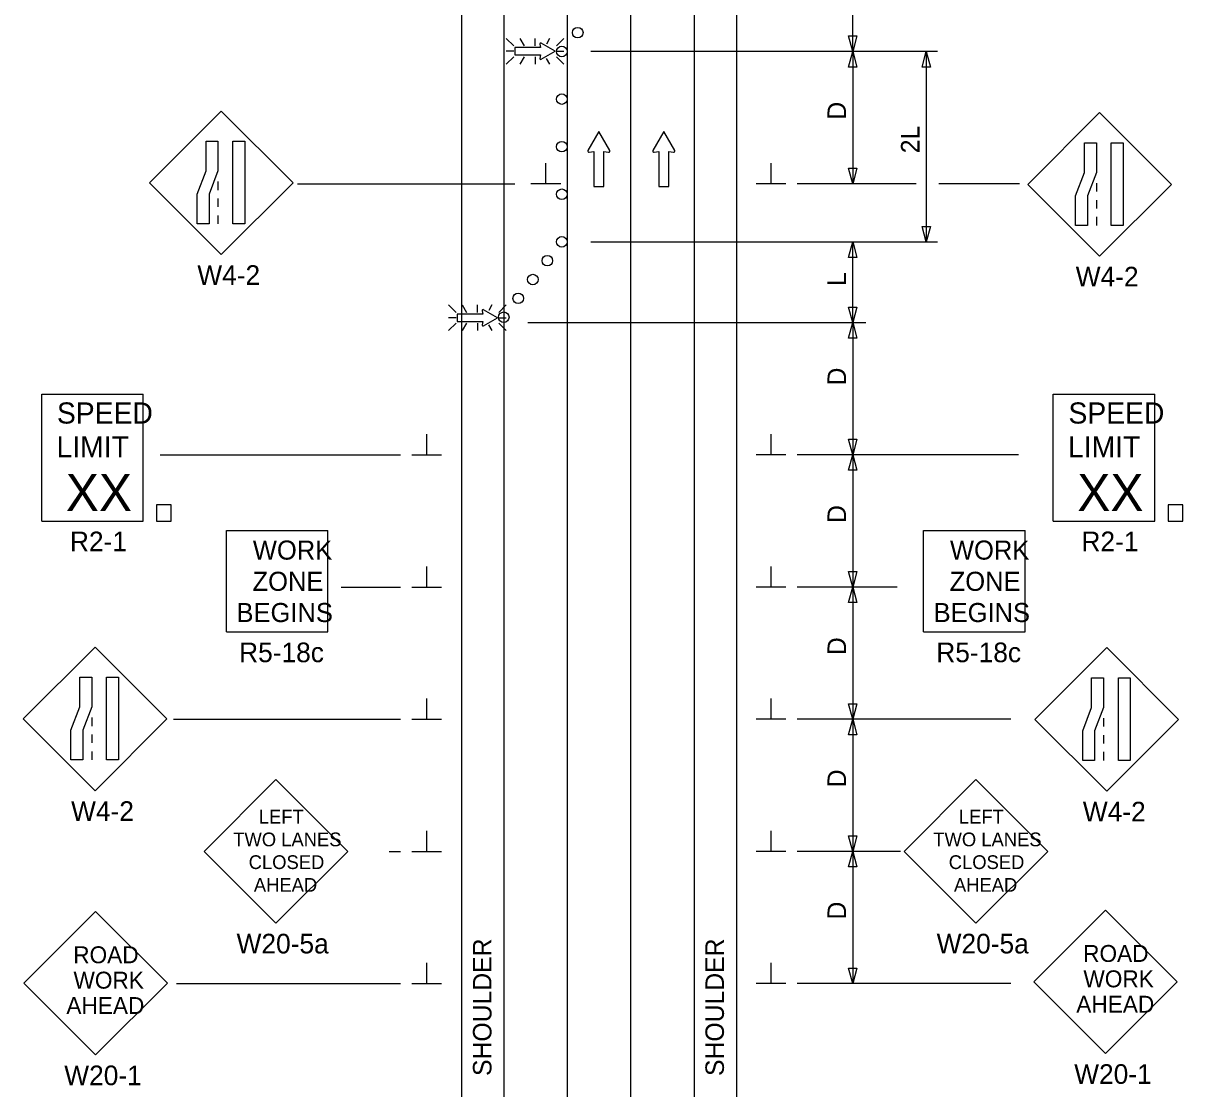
# Model space of a CAD drawing. Extents: x 16745 to 18475, y 7012 to 8195.
# Drawn here: x 16821.7 to 17260.2, y 7436.3 to 7839.4 of the extents above; entities that cross this region are included whole.
import ezdxf

# ---------------------------------------------------------------- set-up
doc = ezdxf.new("R2010")
doc.units = 0
for name, color, linetype in [('ALI_LEGAL_EX', 7, 'Continuous'), ('MT_SCRATCH_LEVEL_E', 7, 'Continuous'), ('PAVT_EDGE_EX', 7, 'Continuous'), ('TRAFFIC_SIGNS_PR', 7, 'Continuous'), ('TYPICAL_TEXT_DIMEN_PR', 7, 'Continuous')]:
    doc.layers.add(name, color=color, linetype=linetype)

msp = doc.modelspace()

# ---------------------------------------------------------------- linework, layer by layer
at = {"layer": 'ALI_LEGAL_EX'}
for p, q in [((17027.37, 8191.42), (17027.37, 7362.23)), ((17051.37, 8191.42), (17051.37, 7362.23)), ((17051.37, 8191.42), (17051.37, 7362.23))]:
    msp.add_line(p, q, dxfattribs=at)
for points in [[(17027.37, 7791.42), (17027.37, 7766.42)], [(17051.37, 7791.42), (17051.37, 7766.42)], [(17027.37, 7691.42), (17027.37, 7666.42)], [(17051.37, 7691.42), (17051.37, 7666.42)], [(17027.37, 7591.42), (17027.37, 7566.42)], [(17051.37, 7591.42), (17051.37, 7566.42)], [(17027.37, 7491.42), (17027.37, 7466.42)], [(17051.37, 7491.42), (17051.37, 7466.42)]]:
    msp.add_lwpolyline(points, dxfattribs=at)
at = {"layer": 'MT_SCRATCH_LEVEL_E'}
for p, q in [((17039.33, 7798.49), (17035.22, 7791.25)), ((17039.33, 7798.49), (17035.22, 7791.25)), ((17043.48, 7791.25), (17039.33, 7798.49)), ((17043.48, 7791.25), (17039.33, 7798.49)), ((17063.89, 7798.49), (17059.78, 7791.25)), ((17063.89, 7798.49), (17059.78, 7791.25)), ((17068.04, 7791.25), (17063.89, 7798.49)), ((17068.04, 7791.25), (17063.89, 7798.49)), ((17035.7, 7790.57), (17037.48, 7790.89)), ((17035.7, 7790.57), (17037.48, 7790.89)), ((17037.48, 7790.89), (17037.48, 7777.63)), ((17037.48, 7790.89), (17037.48, 7777.63)), ((17041.22, 7777.63), (17041.22, 7790.89)), ((17041.22, 7790.89), (17043, 7790.57)), ((17041.22, 7777.63), (17041.22, 7790.89)), ((17041.22, 7790.89), (17043, 7790.57)), ((17060.26, 7790.57), (17062.04, 7790.89)), ((17060.26, 7790.57), (17062.04, 7790.89)), ((17062.04, 7790.89), (17062.04, 7777.63)), ((17062.04, 7790.89), (17062.04, 7777.63)), ((17065.78, 7777.63), (17065.78, 7790.89)), ((17065.78, 7790.89), (17067.56, 7790.57)), ((17065.78, 7777.63), (17065.78, 7790.89)), ((17065.78, 7790.89), (17067.56, 7790.57)), ((17037.48, 7777.63), (17041.22, 7777.63)), ((17037.48, 7777.63), (17041.22, 7777.63)), ((17062.04, 7777.63), (17065.78, 7777.63)), ((17062.04, 7777.63), (17065.78, 7777.63))]:
    msp.add_line(p, q, dxfattribs=at)
for centre, start, end in [((17035.63, 7791.03), 150.4248, 279.9638), ((17035.63, 7791.03), 150.4248, 279.9638), ((17043.07, 7791.03), 260.0362, 29.7731), ((17043.07, 7791.03), 260.0362, 29.7731), ((17060.19, 7791.03), 150.4248, 279.9638), ((17060.19, 7791.03), 150.4248, 279.9638), ((17067.63, 7791.03), 260.0362, 29.7731), ((17067.63, 7791.03), 260.0362, 29.7731)]:
    msp.add_arc(centre, 0.463, start, end, dxfattribs=at)
at = {"layer": 'PAVT_EDGE_EX'}
for p, q in [((16987.37, 8191.42), (16987.37, 7362.23)), ((17003.37, 8191.42), (17003.37, 7362.23)), ((17003.37, 8191.42), (17003.37, 7362.23)), ((17075.37, 8191.42), (17075.37, 7362.23)), ((17091.37, 8191.42), (17091.37, 7362.23))]:
    msp.add_line(p, q, dxfattribs=at)
at = {"layer": 'TRAFFIC_SIGNS_PR'}
for p, q in [((17007.14, 7830.81), (17004.32, 7833.63)), ((17009.44, 7833.63), (17011.06, 7830.81)), ((17015.22, 7830.81), (17015.22, 7833.63)), ((17020.69, 7833.63), (17019.49, 7831.53)), ((17026.13, 7833.62), (17023.31, 7830.81)), ((17007.14, 7828.77), (17004.32, 7828.77)), ((17023.31, 7828.77), (17026.13, 7828.77)), ((17007.14, 7826.74), (17004.32, 7823.92)), ((17011.09, 7826.74), (17009.46, 7823.92)), ((17015.22, 7826.74), (17015.22, 7823.92)), ((17019.41, 7826.11), (17020.67, 7823.92)), ((17026.13, 7823.92), (17023.31, 7826.74)), ((16896.54, 7806.17), (16869.38, 7779.01)), ((16923.69, 7779.01), (16896.54, 7806.17)), ((17228.73, 7805.57), (17201.58, 7778.42)), ((17255.89, 7778.42), (17228.73, 7805.57)), ((16895.29, 7779.5), (16895.29, 7776.3)), ((16869.38, 7779.01), (16896.54, 7751.86)), ((16896.54, 7751.86), (16923.69, 7779.01)), ((17201.58, 7778.42), (17228.73, 7751.27)), ((17227.49, 7778.91), (17227.49, 7775.71)), ((17228.73, 7751.27), (17255.89, 7778.42)), ((16895.29, 7773.1), (16895.29, 7769.9)), ((17227.49, 7772.51), (17227.49, 7769.31)), ((16895.29, 7766.7), (16895.29, 7763.5)), ((17227.49, 7766.11), (17227.49, 7762.91)), ((16985.35, 7730.01), (16982.53, 7732.83)), ((16987.65, 7732.83), (16989.28, 7730.01)), ((16993.44, 7730.01), (16993.44, 7732.83)), ((16998.9, 7732.83), (16997.7, 7730.73)), ((17004.34, 7732.82), (17001.52, 7730.01)), ((16985.35, 7727.98), (16982.53, 7727.98)), ((17001.52, 7727.98), (17004.34, 7727.98)), ((16985.35, 7725.94), (16982.53, 7723.12)), ((16989.3, 7725.94), (16987.67, 7723.12)), ((16993.44, 7725.94), (16993.44, 7723.12)), ((16997.62, 7725.31), (16998.88, 7723.12)), ((17004.34, 7723.12), (17001.52, 7725.94)), ((16828.66, 7699.1), (16867.06, 7699.1)), ((16828.66, 7651.1), (16828.66, 7699.1)), ((16867.06, 7651.1), (16867.06, 7699.1)), ((17211.17, 7699.1), (17249.57, 7699.1)), ((17211.17, 7651.1), (17211.17, 7699.1)), ((17249.57, 7651.1), (17249.57, 7699.1)), ((16828.66, 7651.1), (16867.06, 7651.1)), ((17211.17, 7651.1), (17249.57, 7651.1)), ((16898.5, 7609.13), (16898.5, 7647.53)), ((16898.5, 7647.53), (16936.9, 7647.53)), ((16936.9, 7609.13), (16936.9, 7647.53)), ((17162.13, 7609.13), (17162.13, 7647.53)), ((17162.13, 7647.53), (17200.53, 7647.53)), ((17200.53, 7609.13), (17200.53, 7647.53)), ((16898.5, 7609.13), (16936.9, 7609.13)), ((17162.13, 7609.13), (17200.53, 7609.13)), ((16848.81, 7603.41), (16821.65, 7576.25)), ((16875.96, 7576.25), (16848.81, 7603.41)), ((17231.43, 7603.2), (17204.27, 7576.05)), ((17258.58, 7576.05), (17231.43, 7603.2)), ((16821.65, 7576.25), (16848.81, 7549.1)), ((16847.56, 7576.74), (16847.56, 7573.54)), ((16848.81, 7549.1), (16875.96, 7576.25)), ((17204.27, 7576.05), (17231.43, 7548.89)), ((17230.18, 7576.54), (17230.18, 7573.34)), ((17231.43, 7548.89), (17258.58, 7576.05)), ((16847.56, 7570.34), (16847.56, 7567.14)), ((17230.18, 7570.14), (17230.18, 7566.94)), ((16847.56, 7563.94), (16847.56, 7560.74)), ((17230.18, 7563.74), (17230.18, 7560.54)), ((16917.22, 7553.28), (16890.07, 7526.12)), ((16944.37, 7526.12), (16917.22, 7553.28)), ((17181.96, 7553.28), (17154.81, 7526.12)), ((17209.11, 7526.12), (17181.96, 7553.28)), ((16890.07, 7526.12), (16917.22, 7498.97)), ((16917.22, 7498.97), (16944.37, 7526.12)), ((17154.81, 7526.12), (17181.96, 7498.97)), ((17181.96, 7498.97), (17209.11, 7526.12)), ((16849.02, 7503.44), (16821.87, 7476.28)), ((16876.18, 7476.28), (16849.02, 7503.44)), ((17230.94, 7503.94), (17203.79, 7476.78)), ((17258.1, 7476.78), (17230.94, 7503.94)), ((16821.87, 7476.28), (16849.02, 7449.13)), ((16849.02, 7449.13), (16876.18, 7476.28)), ((17203.79, 7476.78), (17230.94, 7449.63)), ((17230.94, 7449.63), (17258.1, 7476.78))]:
    msp.add_line(p, q, dxfattribs=at)
for points in [[(17017.05, 7831.46), (17017.28, 7830.16), (17007.56, 7830.16), (17007.56, 7827.42), (17017.28, 7827.42), (17017.05, 7826.11)], [(17017.55, 7825.76), (17022.86, 7828.77), (17017.55, 7831.82)], [(16995.26, 7730.66), (16995.49, 7729.36), (16985.77, 7729.36), (16985.77, 7726.62), (16995.49, 7726.62), (16995.26, 7725.31)], [(16995.76, 7724.96), (17001.07, 7727.98), (16995.76, 7731.02)]]:
    msp.add_lwpolyline(points, dxfattribs=at)
for points in [[(16895.29, 7794.75), (16895.29, 7783.57), (16891.95, 7774.69), (16891.95, 7763.5), (16887.45, 7763.5), (16887.45, 7774.69), (16890.8, 7783.57), (16890.8, 7794.75)], [(16905.43, 7794.75), (16905.43, 7763.5), (16900.93, 7763.5), (16900.93, 7794.75)], [(17227.49, 7794.16), (17227.49, 7782.98), (17224.14, 7774.09), (17224.14, 7762.91), (17219.65, 7762.91), (17219.65, 7774.09), (17222.99, 7782.98), (17222.99, 7794.16)], [(17237.62, 7794.16), (17237.62, 7762.91), (17233.13, 7762.91), (17233.13, 7794.16)], [(16872.07, 7651.1), (16877.67, 7651.1), (16877.67, 7657.27), (16872.07, 7657.27)], [(17254.59, 7651.1), (17260.18, 7651.1), (17260.18, 7657.27), (17254.59, 7657.27)], [(16847.56, 7591.99), (16847.56, 7580.81), (16844.22, 7571.93), (16844.22, 7560.74), (16839.72, 7560.74), (16839.72, 7571.93), (16843.07, 7580.81), (16843.07, 7591.99)], [(16857.7, 7591.99), (16857.7, 7560.74), (16853.2, 7560.74), (16853.2, 7591.99)], [(17230.18, 7591.78), (17230.18, 7580.6), (17226.83, 7571.72), (17226.83, 7560.54), (17222.34, 7560.54), (17222.34, 7571.72), (17225.68, 7580.6), (17225.68, 7591.78)], [(17240.31, 7591.78), (17240.31, 7560.54), (17235.82, 7560.54), (17235.82, 7591.78)]]:
    msp.add_lwpolyline(points, close=True, dxfattribs=at)
for centre in [(17031.36, 7835.84), (17025.36, 7828.7), (17025.36, 7810.7), (17025.36, 7792.7), (17025.36, 7774.7), (17025.36, 7756.7), (17019.87, 7749.57), (17014.37, 7742.44), (17008.87, 7735.32), (17003.38, 7728.19)]:
    msp.add_circle(centre, 2, dxfattribs=at)
for centre, start, end in [((17017.39, 7831.52), 61.4833, 189.9593), ((17017.39, 7826.06), 170.7308, 298.8916), ((16995.6, 7730.72), 61.4833, 189.9593), ((16995.6, 7725.26), 170.7308, 298.8916)]:
    msp.add_arc(centre, 0.341, start, end, dxfattribs=at)
at = {"layer": 'TYPICAL_TEXT_DIMEN_PR'}
for p, q in [((17135.37, 7828.7), (17135.37, 7859.27)), ((17135.37, 7828.7), (17133.8, 7834.57)), ((17133.8, 7834.57), (17135.37, 7834.57)), ((17135.37, 7834.57), (17136.94, 7834.57)), ((17136.94, 7834.57), (17135.37, 7828.7)), ((17167.41, 7828.7), (17036.26, 7828.7)), ((17133.8, 7822.84), (17135.37, 7828.7)), ((17135.37, 7828.7), (17135.37, 7778.7)), ((17135.37, 7828.7), (17136.94, 7822.84)), ((17161.6, 7822.84), (17163.17, 7828.7)), ((17163.17, 7828.7), (17164.74, 7822.84)), ((17163.17, 7828.7), (17163.17, 7756.7)), ((17135.37, 7822.84), (17133.8, 7822.84)), ((17136.94, 7822.84), (17135.37, 7822.84)), ((17163.17, 7822.84), (17161.6, 7822.84)), ((17164.74, 7822.84), (17163.17, 7822.84)), ((17019.29, 7778.7), (17019.29, 7786.49)), ((17104.49, 7778.7), (17104.49, 7786.49)), ((17135.37, 7778.7), (17133.8, 7784.57)), ((17133.8, 7784.57), (17135.37, 7784.57)), ((17135.37, 7784.57), (17136.94, 7784.57)), ((17136.94, 7784.57), (17135.37, 7778.7)), ((17163.17, 7783.57), (17163.17, 7779.8)), ((16925.37, 7778.7), (17007.56, 7778.7)), ((17024.92, 7778.7), (17013.67, 7778.7)), ((17110.12, 7778.7), (17098.87, 7778.7)), ((17159.35, 7778.7), (17114.37, 7778.7)), ((17198.45, 7778.7), (17167.86, 7778.7)), ((17163.17, 7756.7), (17161.6, 7762.57)), ((17161.6, 7762.57), (17163.17, 7762.57)), ((17163.17, 7762.57), (17164.74, 7762.57)), ((17164.74, 7762.57), (17163.17, 7756.7)), ((17036.26, 7756.7), (17167.41, 7756.7)), ((17133.8, 7750.84), (17135.37, 7756.7)), ((17135.37, 7726.14), (17135.37, 7756.7)), ((17135.37, 7756.7), (17136.94, 7750.84)), ((17135.37, 7750.84), (17133.8, 7750.84)), ((17136.94, 7750.84), (17135.37, 7750.84)), ((17135.37, 7726.14), (17133.8, 7732)), ((17133.8, 7732), (17135.37, 7732)), ((17135.37, 7732), (17136.94, 7732)), ((17136.94, 7732), (17135.37, 7726.14)), ((17012.53, 7726.14), (17140.37, 7726.14)), ((17133.8, 7720.28), (17135.37, 7726.14)), ((17133.8, 7720.28), (17135.37, 7726.14)), ((17135.37, 7726.14), (17135.37, 7676.14)), ((17135.37, 7726.14), (17136.94, 7720.28)), ((17135.37, 7726.14), (17136.94, 7720.28)), ((17135.37, 7720.28), (17133.8, 7720.28)), ((17135.37, 7720.28), (17133.8, 7720.28)), ((17136.94, 7720.28), (17135.37, 7720.28)), ((17136.94, 7720.28), (17135.37, 7720.28)), ((16974.24, 7676.14), (16974.24, 7683.92)), ((17104.49, 7676.14), (17104.49, 7683.92)), ((17135.37, 7676.14), (17133.8, 7682)), ((17133.8, 7682), (17135.37, 7682)), ((17135.37, 7676.14), (17133.8, 7682)), ((17133.8, 7682), (17135.37, 7682)), ((17135.37, 7682), (17136.94, 7682)), ((17136.94, 7682), (17135.37, 7676.14)), ((17135.37, 7682), (17136.94, 7682)), ((17136.94, 7682), (17135.37, 7676.14)), ((16873.41, 7676.14), (16964.37, 7676.14)), ((16968.62, 7676.14), (16979.87, 7676.14)), ((17110.12, 7676.14), (17098.87, 7676.14)), ((17198.02, 7676.14), (17114.37, 7676.14)), ((17133.8, 7670.28), (17135.37, 7676.14)), ((17133.8, 7670.28), (17135.37, 7676.14)), ((17135.37, 7676.14), (17135.37, 7626.14)), ((17135.37, 7676.14), (17136.94, 7670.28)), ((17135.37, 7676.14), (17136.94, 7670.28)), ((17135.37, 7670.28), (17133.8, 7670.28)), ((17135.37, 7670.28), (17133.8, 7670.28)), ((17136.94, 7670.28), (17135.37, 7670.28)), ((17136.94, 7670.28), (17135.37, 7670.28)), ((16974.24, 7626.14), (16974.24, 7633.92)), ((17104.49, 7626.14), (17104.49, 7633.92)), ((17135.37, 7626.14), (17133.8, 7632)), ((17133.8, 7632), (17135.37, 7632)), ((17135.37, 7626.14), (17133.8, 7632)), ((17133.8, 7632), (17135.37, 7632)), ((17135.37, 7632), (17136.94, 7632)), ((17136.94, 7632), (17135.37, 7626.14)), ((17135.37, 7632), (17136.94, 7632)), ((17136.94, 7632), (17135.37, 7626.14)), ((16941.96, 7626.14), (16964.37, 7626.14)), ((16968.62, 7626.14), (16979.87, 7626.14)), ((17110.12, 7626.14), (17098.87, 7626.14)), ((17152.18, 7626.14), (17114.37, 7626.14)), ((17133.8, 7620.28), (17135.37, 7626.14)), ((17135.37, 7626.14), (17136.94, 7620.28)), ((17135.37, 7626.14), (17135.37, 7576.14)), ((17135.37, 7620.28), (17133.8, 7620.28)), ((17136.94, 7620.28), (17135.37, 7620.28)), ((16974.24, 7576.14), (16974.24, 7583.92)), ((17104.49, 7576.14), (17104.49, 7583.92)), ((17135.37, 7576.14), (17133.8, 7582)), ((17133.8, 7582), (17135.37, 7582)), ((17135.37, 7576.14), (17133.8, 7582)), ((17133.8, 7582), (17135.37, 7582)), ((17135.37, 7582), (17136.94, 7582)), ((17136.94, 7582), (17135.37, 7576.14)), ((17135.37, 7582), (17136.94, 7582)), ((17136.94, 7582), (17135.37, 7576.14)), ((16878.45, 7576.14), (16964.37, 7576.14)), ((16968.62, 7576.14), (16979.87, 7576.14)), ((17110.12, 7576.14), (17098.87, 7576.14)), ((17195.19, 7576.14), (17114.37, 7576.14)), ((17133.8, 7570.28), (17135.37, 7576.14)), ((17133.8, 7570.28), (17135.37, 7576.14)), ((17135.37, 7576.14), (17135.37, 7526.14)), ((17135.37, 7576.14), (17136.94, 7570.28)), ((17135.37, 7576.14), (17136.94, 7570.28)), ((17135.37, 7570.28), (17133.8, 7570.28)), ((17135.37, 7570.28), (17133.8, 7570.28)), ((17136.94, 7570.28), (17135.37, 7570.28)), ((17136.94, 7570.28), (17135.37, 7570.28)), ((16974.24, 7526.14), (16974.24, 7533.92)), ((17104.49, 7526.14), (17104.49, 7533.92)), ((17135.37, 7526.14), (17133.8, 7532)), ((17133.8, 7532), (17135.37, 7532)), ((17135.37, 7526.14), (17133.8, 7532)), ((17133.8, 7532), (17135.37, 7532)), ((17135.37, 7532), (17136.94, 7532)), ((17136.94, 7532), (17135.37, 7526.14)), ((17135.37, 7532), (17136.94, 7532)), ((17136.94, 7532), (17135.37, 7526.14)), ((16960.01, 7526.14), (16964.37, 7526.14)), ((16968.62, 7526.14), (16979.87, 7526.14)), ((17110.12, 7526.14), (17098.87, 7526.14)), ((17153.37, 7526.14), (17114.37, 7526.14)), ((17133.8, 7520.28), (17135.37, 7526.14)), ((17135.37, 7526.14), (17135.37, 7476.14)), ((17135.37, 7526.14), (17136.94, 7520.28)), ((17135.37, 7520.28), (17133.8, 7520.28)), ((17136.94, 7520.28), (17135.37, 7520.28)), ((16974.24, 7476.14), (16974.24, 7483.92)), ((17104.49, 7476.14), (17104.49, 7483.92)), ((17135.37, 7476.14), (17133.8, 7482)), ((17133.8, 7482), (17135.37, 7482)), ((17135.37, 7482), (17136.94, 7482)), ((17136.94, 7482), (17135.37, 7476.14)), ((16879.65, 7476.14), (16964.37, 7476.14)), ((16968.62, 7476.14), (16979.87, 7476.14)), ((17110.12, 7476.14), (17098.87, 7476.14)), ((17195.19, 7476.14), (17114.37, 7476.14))]:
    msp.add_line(p, q, dxfattribs=at)

# ---------------------------------------------------------------- texts
at = {"layer": 'TRAFFIC_SIGNS_PR'}
for s, height, p in [('W4-2', 7.44, (16887.5, 7740.42)), ('W4-2', 7.44, (17219.69, 7739.83)), ('SPEED', 8, (16834.42, 7687.96)), ('SPEED', 8, (17216.94, 7687.96)), ('LIMIT', 8, (16834.26, 7675.16)), ('LIMIT', 8, (17216.78, 7675.16)), ('XX', 14.031, (16837.77, 7654.86)), ('XX', 14.031, (17220.28, 7654.86)), ('R2-1', 7.44, (16839.33, 7639.66)), ('WORK', 7.217, (16908.5, 7636.5)), ('WORK', 7.217, (17172.13, 7636.5)), ('R2-1', 7.44, (17221.85, 7639.66)), ('ZONE', 7.217, (16908.38, 7624.69)), ('ZONE', 7.217, (17172.02, 7624.69)), ('BEGINS', 7.217, (16902.31, 7612.88)), ('BEGINS', 7.217, (17165.94, 7612.88)), ('R5-18c', 7.44, (16903.31, 7597.69)), ('R5-18c', 7.44, (17166.95, 7597.69)), ('W4-2', 7.44, (16839.76, 7537.66)), ('W4-2', 7.44, (17222.38, 7537.45)), ('LEFT', 5.2, (16910.75, 7536.66)), ('LEFT', 5.2, (17175.5, 7536.66)), ('TWO LANES', 5.2, (16901.08, 7528.06)), ('TWO LANES', 5.2, (17165.82, 7528.06)), ('CLOSED', 5.2, (16906.93, 7519.46)), ('CLOSED', 5.2, (17171.67, 7519.46)), ('AHEAD', 5.2, (16908.88, 7510.86)), ('AHEAD', 5.2, (17173.62, 7510.86)), ('W20-5a', 7.44, (16902.36, 7487.53)), ('W20-5a', 7.44, (17167.1, 7487.53)), ('ROAD', 6.4, (16840.57, 7483.82)), ('ROAD', 6.4, (17222.49, 7484.32)), ('WORK', 6.4, (16840.68, 7474.22)), ('WORK', 6.4, (17222.6, 7474.72)), ('AHEAD', 6.4, (16837.98, 7464.62)), ('AHEAD', 6.4, (17219.9, 7465.12)), ('W20-1', 7.44, (16837.19, 7437.69)), ('W20-1', 7.44, (17219.11, 7438.19))]:
    msp.add_text(s, height=height, dxfattribs=at).set_placement(p)
at = {"layer": 'TYPICAL_TEXT_DIMEN_PR'}
for s, p in [('D', (17132.81, 7802.92)), ('2L', (17160.61, 7790.21)), ('L', (17132.81, 7740)), ('D', (17132.81, 7702.37)), ('D', (17132.81, 7650.36)), ('D', (17132.81, 7600.36)), ('D', (17132.81, 7550.36)), ('D', (17132.81, 7500.36)), ('SHOULDER', (16998.74, 7441.17)), ('SHOULDER', (17086.65, 7441.17))]:
    msp.add_text(s, height=7, rotation=90, dxfattribs=at).set_placement(p)

doc.saveas('drawing.dxf')
